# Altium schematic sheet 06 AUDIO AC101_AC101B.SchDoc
size 513 x 386 mm
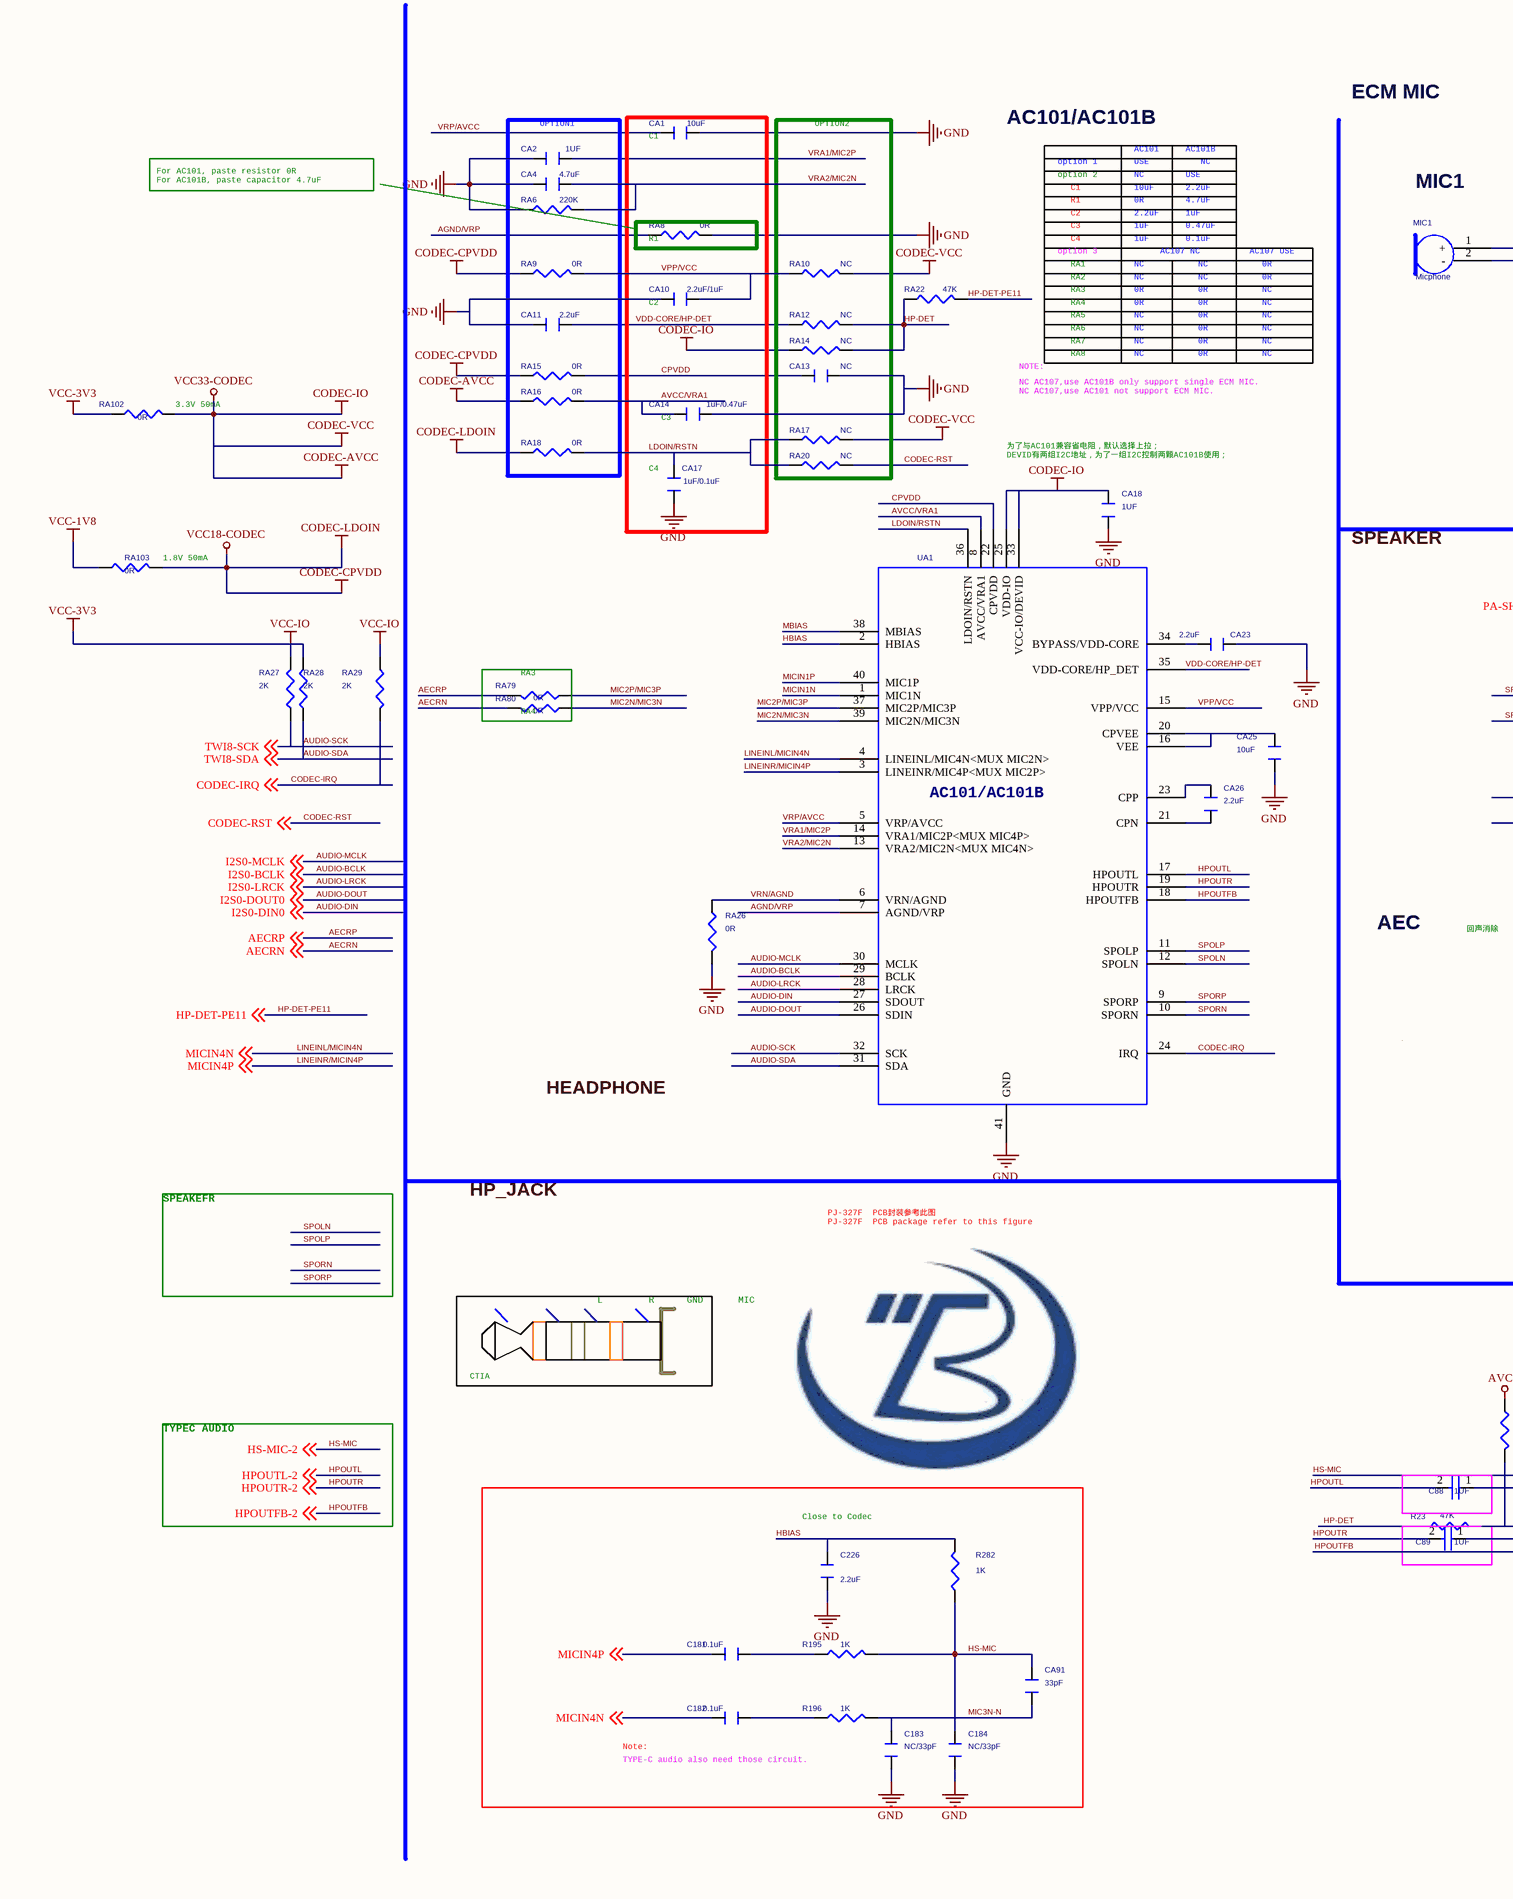
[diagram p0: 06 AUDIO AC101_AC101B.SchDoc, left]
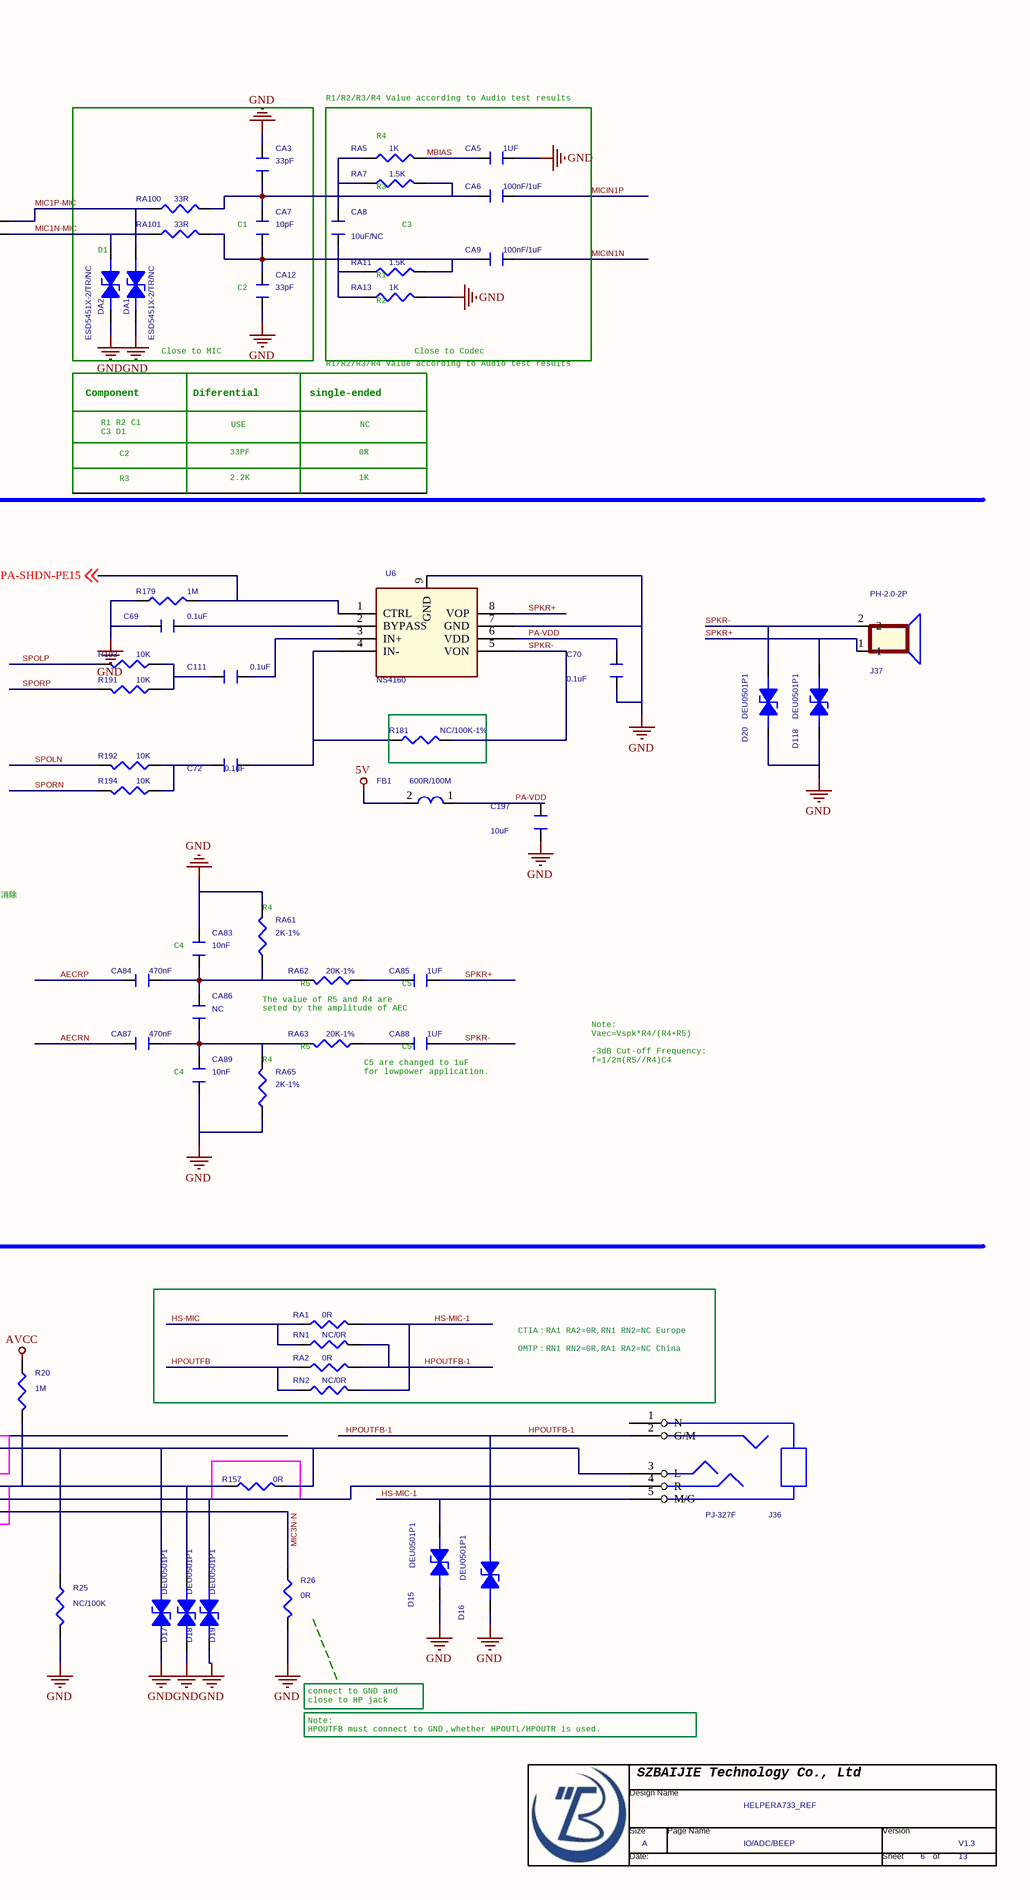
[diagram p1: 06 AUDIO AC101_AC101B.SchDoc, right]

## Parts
*  Page Count: 13  Page Number: 6  Page Size: A  Title: HELPERA733_REF  RevCode: V1.3  Doc: IO/ADC/BEEP  (hidden comment: TitleBlock0-BJ)  (graphical)
C69  0.1uF  [C0402]
C70  0.1uF  [C0402]
C72  0.1uF  [C0402]
C88  1UF  [C0402]
C89  1UF  [C0402]
C111  0.1uF  [C0402]
C181  0.1uF  [C0402]
C182  0.1uF  [C0402]
C183  NC/33pF  [C0402]
C184  NC/33pF  [C0402]
C197  10uF  [C0402]
C226  2.2uF  [C0402]
CA1  10uF  [C0603]
CA2  1UF  [C0402]
CA3  33pF  [C0402]
CA4  4.7uF  [C0402]
CA5  1UF  [C0402]
CA6  100nF/1uF  [C0402]
CA7  10pF  [C0402]
CA8  10uF/NC  [C0603]
CA9  100nF/1uF  [C0402]
CA10  2.2uF/1uF  [C0402]
CA11  2.2uF  [C0402]
CA12  33pF  [C0402]
CA13  NC  [C0402]
CA14  1uF/0.47uF  [C0402]
CA17  1uF/0.1uF  [C0402]
CA18  1UF  [C0402]
CA23  2.2uF  [C0402]
CA25  10uF  [C0603]
CA26  2.2uF  [C0402]
CA83  10nF  [C0402]
CA84  470nF  [C0402]
CA85  1UF  [C0402]
CA86  NC  [C0402]
CA87  470nF  [C0402]
CA88  1UF  [C0402]
CA89  10nF  [C0402]
CA91  33pF  [C0402]
D15  DEU0501P1  [ESD0402]
D16  DEU0501P1  [ESD0402]
D17  DEU0501P1  [ESD0402]
D18  DEU0501P1  [ESD0402]
D19  DEU0501P1  [ESD0402]
D20  DEU0501P1  [ESD0402]
D118  DEU0501P1  [ESD0402]
DA1  ESD5451X-2/TR/NC  [ESD0402]
DA2  ESD5451X-2/TR/NC  [ESD0402]
FB1  600R/100M  [L0603]
J36  PJ-327F  [PJ381-2]
J37  PH-2.0-2P  [SPEAKER]
MIC1  Micphone  [Micphone Connector]
R20  1M  [R0402]
R23  47K  [R0402]
R25  NC/100K  [R0402]
R26  0R  [R0402]
R157  0R  [R0402]
R179  1M  [R0402]
R181  NC/100K-1%  [R0402]
R191  10K  [R0402]
R192  10K  [R0402]
R193  10K  [R0402]
R194  10K  [R0402]
R195  1K  [R0402]
R196  1K  [R0402]
R282  1K  [R0402]
RA1  0R  [R0402]
RA2  0R  [R0402]
RA5  1K  [R0402]
RA6  220K  [C0402]
RA7  1.5K  [R0402]
RA8  0R  [R0402]
RA9  0R  [R0402]
RA10  NC  [R0402]
RA11  1.5K  [R0402]
RA12  NC  [R0402]
RA13  1K  [R0402]
RA14  NC  [R0402]
RA15  0R  [R0402]
RA16  0R  [R0402]
RA17  NC  [R0402]
RA18  0R  [R0402]
RA20  NC  [R0402]
RA22  47K  [R0402]
RA26  0R  [R0402]
RA27  2K  [R0402]
RA28  2K  [R0402]
RA29  2K  [R0402]
RA61  2K-1%  [R0603]
RA62  20K-1%  [R0603]
RA63  20K-1%  [R0603]
RA65  2K-1%  [R0603]
RA79  0R  [R0402]
RA80  0R  [R0402]
RA100  33R  [R0402]
RA101  33R  [R0402]
RA102  0R  [R0402]
RA103  0R  [R0402]
RN1  NC/0R  [R0402]
RN2  NC/0R  [R0402]
U6  NS4160  [ESOP-8]
UA1  REFERENCE: UA1  [QFN40]  (hidden comment: AC101)

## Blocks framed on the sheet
OPTION1: CA2 CA4 CA11 RA6 RA9 RA15 RA16 RA18
OPTION2: CA13 RA10 RA12 RA14 RA17 RA20
R1: RA8

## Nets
5V: FB1.2
AVCC: R20.1
CODEC-AVCC: CA18.2 RA10.2 RA14.1 RA16.1 RA17.2 RA102.2 UA1.25(VDD-IO) UA1.33(VCC-IO/DEVID)  [also labelled CODEC-IO, CODEC-VCC, VCC33-CODEC]
CODEC-CPVDD: RA9.1 RA15.1 RA18.1 RA103.2  [also labelled CODEC-LDOIN, VCC18-CODEC]
GND: C69.2 C70.2 C183.2 C184.2 C197.2 C226.1 CA1.1 CA2.2 CA3.1 CA4.1 CA5.1 CA10.2 CA11.2 CA12.2 CA13.2 CA14.2 CA17.2 CA18.1 CA23.2 CA25.2 CA83.1 CA89.2 D15.1(ANODE) D16.1(ANODE) D17.1(ANODE) D18.1(ANODE) D19.1(ANODE) D20.1(ANODE) D118.1(ANODE) DA1.1(ANODE) DA2.1(ANODE) R25.2 R26.2 R179.1 RA6.1 RA8.2 RA13.2 RA26.2 RA61.2 RA65.1 U6.7(GND) U6.9(GND) UA1.41(GND)
VCC-1V8: RA103.1
VCC-3V3: RA27.2 RA28.2 RA29.1 RA102.1  [also labelled VCC-IO]
AECRN: CA87.2 RA80.1 ; off-sheet AECRN
AECRP: CA84.2 RA79.1 ; off-sheet AECRP
AGND/VRP: RA8.1 UA1.7(AGND/VRP)
AUDIO-BCLK: UA1.29(BCLK) ; off-sheet I2S0-BCLK  [also labelled I2S0-BCLK]
AUDIO-DIN: UA1.27(SDOUT) ; off-sheet I2S0-DIN0  [also labelled I2S0-DIN0]
AUDIO-DOUT: UA1.26(SDIN) ; off-sheet I2S0-DOUT0  [also labelled I2S0-DOUT0]
AUDIO-LRCK: UA1.28(LRCK) ; off-sheet I2S0-LRCK  [also labelled I2S0-LRCK]
AUDIO-MCLK: UA1.30(MCLK) ; off-sheet I2S0-MCLK  [also labelled I2S0-MCLK]
AUDIO-SCK: RA27.1 RA28.1 UA1.31(SDA) UA1.32(SCK) ; off-sheet TWI8-SCK, off-sheet TWI8-SDA  [also labelled AUDIO-SDA, TWI8-SCK, TWI8-SDA]
AVCC/VRA1: CA14.1 RA16.2 UA1.8(AVCC/VRA1)
CODEC-IRQ: RA29.2 UA1.24(IRQ) ; off-sheet CODEC-IRQ
CODEC-RST: RA20.2 ; off-sheet CODEC-RST
CPVDD: CA13.1 RA15.2 UA1.22(CPVDD)
HBIAS: C226.2 R282.2 UA1.2(HBIAS)
HP-DET: R23.1 RA12.2 RA14.2 RA22.1
HP-DET-PE11: RA22.2 ; off-sheet HP-DET-PE11
HPOUTFB: C183.1 CA91.2 R26.1 R196.2 RA2.1 RN2.1 UA1.18(HPOUTFB) ; off-sheet HPOUTFB-2  [also labelled HPOUTFB-2, MIC3N-N]
HPOUTFB-1: D16.2(CATHODE) J36.2(G/M) RA2.2 RN1.2
HPOUTL: C88.2 UA1.17(HPOUTL) ; off-sheet HPOUTL-2  [also labelled HPOUTL-2]
HPOUTR: C89.2 UA1.19(HPOUTR) ; off-sheet HPOUTR-2  [also labelled HPOUTR-2]
HS-MIC: C184.1 CA91.1 R195.2 R282.1 RA1.1 RN1.1 ; off-sheet HS-MIC-2  [also labelled HS-MIC-2]
HS-MIC-1: D15.2(CATHODE) J36.5(M/G) RA1.2 RN2.2
LDOIN/RSTN: CA17.1 RA17.1 RA18.2 RA20.1 UA1.36(LDOIN/RSTN)
LINEINL/MICIN4N: C182.1 UA1.4(LINEINL/MIC4N<MUX_MIC2N>) ; off-sheet MICIN4N  [also labelled MICIN4N]
LINEINR/MICIN4P: C181.1 UA1.3(LINEINR/MIC4P<MUX_MIC2P>) ; off-sheet MICIN4P  [also labelled MICIN4P]
MBIAS: CA5.2 RA5.2 UA1.38(MBIAS)
MIC1N-MIC: DA2.2(CATHODE) MIC1.2(-) RA101.1
MIC1P-MIC: DA1.2(CATHODE) MIC1.1(+) RA100.1
MIC2N/MIC3N: RA80.2 UA1.39(MIC2N/MIC3N)
MIC2P/MIC3P: RA79.2 UA1.37(MIC2P/MIC3P)
MICIN1N: CA9.1 UA1.1(MIC1N)
MICIN1P: CA6.1 UA1.40(MIC1P)
PA-SHDN-PE15: R179.2 U6.1(CTRL) ; off-sheet PA-SHDN-PE15
PA-VDD: C70.1 C197.1 FB1.1 U6.6(VDD)
SPKR+: CA85.1 D118.2(CATHODE) J37.1 U6.8(VOP)
SPKR-: CA88.1 D20.2(CATHODE) J37.2 R181.2 U6.5(VON)
SPOLN: R192.1 UA1.12(SPOLN)
SPOLP: R193.1 UA1.11(SPOLP)
SPORN: R194.1 UA1.10(SPORN)
SPORP: R191.1 UA1.9(SPORP)
VDD-CORE/HP-DET: CA11.1 RA12.1 UA1.35(VDD-CORE/HP_DET)
VPP/VCC: CA10.1 RA9.2 RA10.1 UA1.15(VPP/VCC)
VRA1/MIC2P: CA2.1 UA1.14(VRA1/MIC2P<MUX_MIC4P>)
VRA2/MIC2N: CA4.2 RA6.2 UA1.13(VRA2/MIC2N<MUX_MIC4N>)
VRN/AGND: RA26.1 UA1.6(VRN/AGND)
VRP/AVCC: CA1.2 UA1.5(VRP/AVCC)
NetC69_1: C69.1 U6.2(BYPASS)
NetC72_1: C72.1 R181.1 U6.4(IN-)
NetC72_2: C72.2 R192.2 R194.2
NetC88_1: C88.1 D17.2(CATHODE) J36.3(L) R25.1 R157.2
NetC89_1: C89.1 D19.2(CATHODE) J36.4(R)
NetC111_1: C111.1 U6.3(IN+)
NetC111_2: C111.2 R191.2 R193.2
NetC181_2: C181.2 R195.1
NetC182_2: C182.2 R196.1
NetCA3_2: CA3.2 CA6.2 CA7.1 RA7.2 RA100.2
NetCA7_2: CA7.2 CA9.2 CA12.1 RA11.2 RA101.2
NetCA8_1: CA8.1 RA5.1 RA7.1
NetCA8_2: CA8.2 RA11.1 RA13.1
NetCA23_1: CA23.1 UA1.34(BYPASS/VDD-CORE)
NetCA25_1: CA25.1 UA1.16(VEE) UA1.20(CPVEE)
NetCA26_1: CA26.1 UA1.23(CPP)
NetCA26_2: CA26.2 UA1.21(CPN)
NetCA83_2: CA83.2 CA84.1 CA86.1 RA61.1 RA62.2
NetCA85_2: CA85.2 RA62.1
NetCA86_2: CA86.2 CA87.1 CA89.1 RA63.2 RA65.2
NetCA88_2: CA88.2 RA63.1
NetD18_2: D18.2(CATHODE) R20.2 R23.2 R157.1

Not connected (* = marked no-connect by the designer): J36 1(N)

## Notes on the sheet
- For AC101, paste resistor 0R
  For AC101B, paste capacitor 4.7uF
- (near CA1) C1
- AC101/AC101B
- AC101
- AC101B
- ECM MIC
- R1/R2/R3/R4 Value according to Audio test results
- option 2
- option 1
- C1
- R1
- C2
- USE
- NC
- 10uF
- 0R
- 2.2uF
- 4.7uF
- 1uF
- MIC1
- (near RA7) R3
- (near RA5) R4
- option 3
- C3
- C4
- RA1
- RA2
- AC107 NC
- 0.47uF
- 0.1uF
- AC107 USE
- (near DA2) D1
- (near CA7) C1
- (near CA10) C2
- RA7
- RA3
- RA4
- RA5
- RA6
- (near CA12) C2
- (near RA11) R1
- (near RA13) R2
- (near RA102) 3.3V 50mA
- NC AC107,use AC101B only support single ECM MIC.
  NC AC107,use AC101 not support ECM MIC.
- NOTE:
- RA8
- Close to MIC
- Close to Codec
- (near CA17) C4
- (near CA14) C3
- (near CA18) 为了与AC101兼容省电阻，默认选择上拉；
  DEVID有两组I2C地址，为了一组I2C控制两颗AC101B使用；
- Component
- R1 R2 C1
  C3 D1
- Diferential
- single-ended
- R3
- 33PF
- 2.2K
- 1K
- (near RA103) 1.8V 50mA
- SPEAKER
- (near RA79) RA3
- (near RA80) RA4
- AEC
- 回声消除
- (near CA83) C4
- (near RA61) R4
- The value of R5 and R4 are
  seted by the amplitude of AEC
- (near RA62) R5
- (near CA85) C5
- Note:
  Vaec=Vspk*R4/(R4+R5)
  -3dB Cut-off Frequency:
  f=1/2π(R5//R4)C4
- HEADPHONE
- (near CA89) C4
- (near RA65) R4
- (near RA63) R5
- C5 are changed to 1uF
  for lowpower application.
- (near CA88) C5
- SPEAKEFR
- HP_JACK
- PJ-327F  PCB封装参考此图
  PJ-327F  PCB package refer to this figure
- L
- R
- GND
- MIC
- CTIA：RA1 RA2=0R,RN1 RN2=NC Europe
  OMTP：RN1 RN2=0R,RA1 RA2=NC China
- TYPEC AUDIO
- CTIA
- (near C226) Close to Codec
- Note:
- (near *) Note:
  HPOUTFB must connect to GND，whether HPOUTL/HPOUTR is used.
- connect to GND and
  close to HP jack
- (near C182) TYPE-C audio also need those circuit.

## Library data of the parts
C69 C70 C111 C197 = C-C0402_Dup1
C72 = CAPACITOR_0_Dup1: options: 4890-2
C88 C89 = CAP NP_0
C181-C184 C226 CA3 CA5-CA7 CA9 CA12 CA83-CA89 CA91 = C-C0402_Dup1: Parameter: C0402-X5R
CA1 CA2 CA10 CA18 = CAPACITOR_0_Dup1: ROOM: POWER; PAGE: 2
CA4 CA17 = CAPACITOR_0: ROOM: AC100; PAGE: 1
CA8 = C-C0603: Parameter: C0402-X5R
CA11 = CAPACITOR_0_Dup1: PAGE: 2; ROOM: POWER
CA13 CA14 CA23 CA25 CA26 = CAPACITOR_0: PAGE: 1; ROOM: AC100
D15-D19 = ESD9B5VL: ID: DE-E0001
D20 D118 = ESD9B5VL: ID: DE-E0001; options: 4890-1
DA1 DA2 = ESD9B5VL_0: Parameter: ESD0402，3PF; ID: DE-E0001
FB1 = INDUCTOR_0_Dup1: RoHS BEAD/600ohm 100Mhz Z=600Ω DCR<0.2Ω 800mA SMT L0603; OriginalSymbolOrigin: (10,0); Pin Numbers Visible: TRUE; Pin Names Visible: FALSE
J36 = PJ381-2_1
J37 = SPEAKER_0
MIC1 = Micphone_0: mypage: 13
R20 R23 R25 R26 R157 RA1 RA2 RN1 RN2 = R-R0402-5%
R179 R181 R195 R196 R282 RA5 RA7 RA11 RA13 RA100 RA101 = R-R0402-5%_Dup3
R191-R194 = RESISTOR: options: 4890-2
RA6 RA8-RA10 RA12 RA14-RA18 RA20 RA22 RA26-RA29 RA102 RA103 = R: ROOM: AC100
RA61-RA63 RA65 = R-R0603-1%
RA79 RA80 = R-R0402-5%_Dup1
U6 = LY8006_1
UA1 = AC101&AC101B V0_1.2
